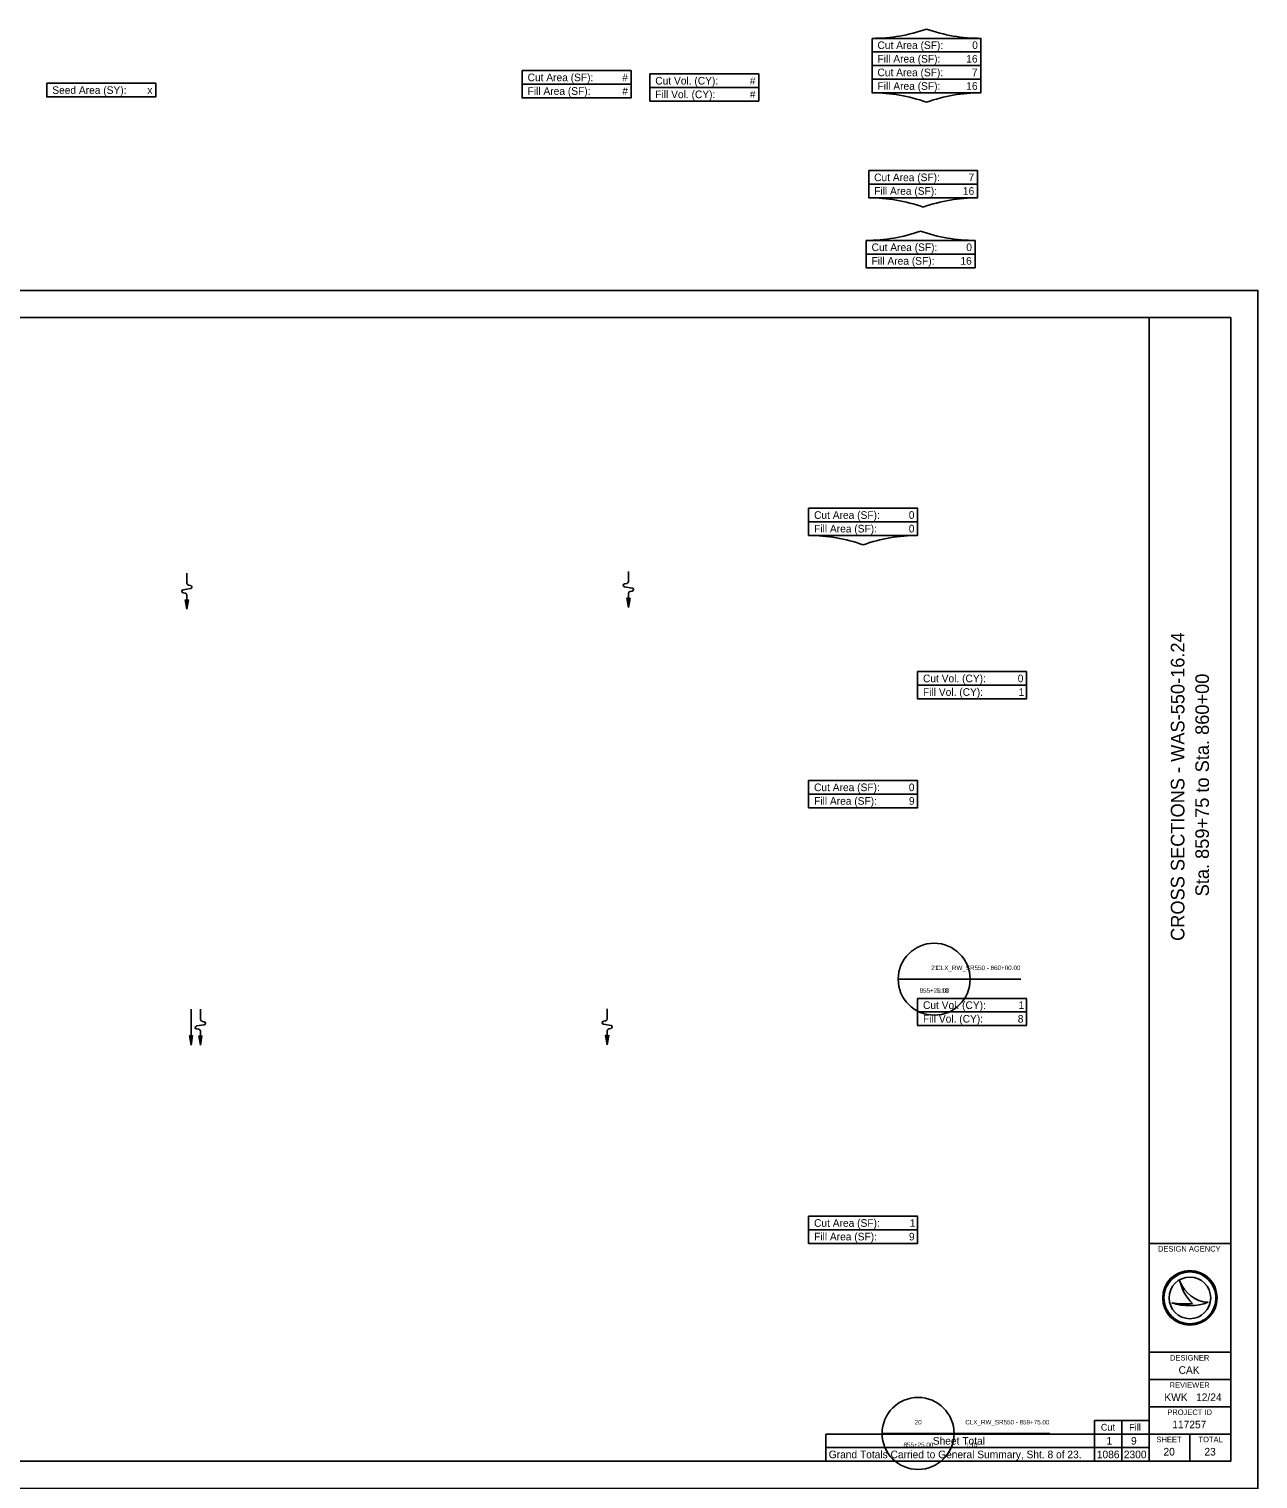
# Model space of a CAD drawing. Extents: x -475 to 76, y 0 to 417.
# Drawn here: x 11.44 to 34, y 198.17 to 224.8 of the extents above; entities that cross this region are included whole.
import ezdxf

# ---------------------------------------------------------------- set-up
doc = ezdxf.new("R2010")
doc.units = 0
for name, color, linetype in [('_CIVIL_CONSTRUCTION', 7, 'Continuous'), ('Default', 7, 'Continuous'), ('RW_P_Esmt_SH', 7, 'Continuous'), ('RW_P_Esmt_TMP', 7, 'Continuous'), ('SC_Scratch1', 7, 'Continuous'), ('SC_Scratch10', 7, 'Continuous'), ('SH_Masking', 7, 'Continuous')]:
    doc.layers.add(name, color=color, linetype=linetype)

msp = doc.modelspace()

# ---------------------------------------------------------------- linework, layer by layer
at = {"layer": '_CIVIL_CONSTRUCTION'}
for p, q in [((27.393, 207.352), (28.716, 207.352)), ((28.061, 207.352), (29.648, 207.352)), ((27.099, 199.01), (28.422, 199.01)), ((27.766, 199.01), (30.181, 199.01))]:
    msp.add_line(p, q, dxfattribs=at)
for centre in [(28.055, 207.352), (27.76, 199.01)]:
    msp.add_circle(centre, 0.661, dxfattribs=at)
at = {"layer": 'Default'}
for p, q in [((14.336, 214.808), (14.336, 214.623)), ((22.411, 214.618), (22.371, 214.611)), ((22.442, 214.84), (22.442, 214.655)), ((14.265, 214.447), (14.305, 214.439)), ((14.405, 214.523), (14.266, 214.502)), ((14.336, 214.402), (14.336, 214.146)), ((14.366, 214.586), (14.406, 214.579)), ((22.372, 214.555), (22.511, 214.534)), ((22.442, 214.178), (22.413, 214.352)), ((22.413, 214.352), (22.413, 214.352)), ((22.442, 214.435), (22.442, 214.178)), ((22.471, 214.351), (22.442, 214.178)), ((22.471, 214.351), (22.471, 214.351)), ((22.512, 214.479), (22.472, 214.471)), ((14.307, 214.319), (14.307, 214.319)), ((14.307, 214.319), (14.336, 214.146)), ((14.336, 214.146), (14.365, 214.32)), ((14.365, 214.32), (14.365, 214.32)), ((14.412, 206.804), (14.412, 206.142)), ((14.584, 206.8), (14.584, 206.615)), ((22.052, 206.809), (22.052, 206.624)), ((14.513, 206.439), (14.553, 206.432)), ((14.653, 206.515), (14.514, 206.495)), ((14.584, 206.395), (14.584, 206.138)), ((14.614, 206.578), (14.654, 206.571)), ((22.022, 206.587), (21.982, 206.58)), ((21.983, 206.524), (22.122, 206.504)), ((22.052, 206.404), (22.052, 206.147)), ((22.123, 206.448), (22.083, 206.441)), ((14.383, 206.315), (14.383, 206.315)), ((14.383, 206.315), (14.412, 206.142)), ((14.412, 206.142), (14.441, 206.316)), ((14.441, 206.316), (14.441, 206.316)), ((14.555, 206.312), (14.555, 206.312)), ((14.555, 206.312), (14.584, 206.138)), ((14.584, 206.138), (14.613, 206.312)), ((14.613, 206.312), (14.613, 206.312)), ((22.052, 206.147), (22.023, 206.321)), ((22.023, 206.321), (22.023, 206.321)), ((22.081, 206.321), (22.052, 206.147)), ((22.081, 206.321), (22.081, 206.321)), ((31, 198.5), (31, 199.25)), ((31.5, 198.5), (31.5, 199.25)), ((26.064, 198.5), (26.064, 199)), ((31, 198.5), (31, 199))]:
    msp.add_line(p, q, dxfattribs=at)
for centre, radius, start, end in [((14.373, 214.623), 0.0375, 180, 259.3803), ((22.376, 214.583), 0.0281, 100.6197, 261.4692), ((22.404, 214.655), 0.0375, 280.6197, 360), ((14.27, 214.474), 0.0281, 98.5308, 259.3803), ((14.298, 214.402), 0.0375, 0, 79.3803), ((14.401, 214.551), 0.0281, 278.5308, 79.3803), ((22.442, 214.396), 0.0527, 236.178, 302.8588), ((22.479, 214.435), 0.0375, 100.6197, 180), ((22.507, 214.507), 0.0281, 280.6197, 81.4692), ((14.335, 214.364), 0.0527, 237.1412, 303.822), ((22.015, 206.624), 0.0375, 280.6197, 360), ((14.518, 206.467), 0.0281, 98.5308, 259.3803), ((14.546, 206.395), 0.0375, 0, 79.3803), ((14.621, 206.615), 0.0375, 180, 259.3803), ((14.649, 206.543), 0.0281, 278.5308, 79.3803), ((21.987, 206.552), 0.0281, 100.6197, 261.4692), ((22.09, 206.404), 0.0375, 100.6197, 180), ((22.118, 206.476), 0.0281, 280.6197, 81.4692), ((14.411, 206.36), 0.0527, 237.1412, 303.822), ((14.583, 206.356), 0.0527, 237.1412, 303.822), ((22.053, 206.365), 0.0527, 236.178, 302.8588)]:
    msp.add_arc(centre, radius, start, end, dxfattribs=at)
at = {"layer": 'RW_P_Esmt_SH'}
msp.add_lwpolyline([(0, 198), (34, 198), (34, 220), (0, 220)], close=True, dxfattribs=at)
at = {"layer": 'RW_P_Esmt_TMP'}
for p, q in [((32, 198.5), (32, 219.5)), ((32, 202.5), (33.5, 202.5)), ((32, 200.5), (33.5, 200.5)), ((32, 200), (33.5, 200)), ((32, 199.5), (33.5, 199.5)), ((32, 199), (33.5, 199))]:
    msp.add_line(p, q, dxfattribs=at)
msp.add_lwpolyline([(1.5, 219.5), (33.5, 219.5), (33.5, 198.5), (1.5, 198.5)], close=True, dxfattribs=at)
at = {"layer": 'SC_Scratch1'}
for p, q in [((26.914, 224.628), (28.914, 224.628)), ((26.914, 224.628), (26.914, 224.128)), ((28.914, 224.628), (26.914, 224.628)), ((28.914, 224.628), (28.914, 224.128)), ((26.914, 224.378), (28.914, 224.378)), ((20.491, 224.036), (22.491, 224.036)), ((20.491, 224.036), (20.491, 223.536)), ((22.491, 224.036), (22.491, 223.536)), ((22.835, 223.975), (24.835, 223.975)), ((22.835, 223.975), (22.835, 223.475)), ((24.835, 223.975), (24.835, 223.475)), ((26.914, 224.128), (28.914, 224.128)), ((26.914, 224.128), (28.914, 224.128)), ((26.914, 224.128), (26.914, 223.628)), ((28.914, 224.128), (28.914, 223.628)), ((11.764, 223.803), (13.764, 223.803)), ((11.764, 223.803), (11.764, 223.553)), ((13.764, 223.803), (13.764, 223.553)), ((20.491, 223.786), (22.491, 223.786)), ((22.835, 223.725), (24.835, 223.725)), ((26.914, 223.878), (28.914, 223.878)), ((11.764, 223.553), (13.764, 223.553)), ((20.491, 223.536), (22.491, 223.536)), ((22.835, 223.475), (24.835, 223.475)), ((26.914, 223.628), (28.914, 223.628)), ((28.914, 223.628), (26.914, 223.628)), ((26.853, 222.201), (28.853, 222.201)), ((26.853, 222.201), (26.853, 221.701)), ((28.853, 222.201), (28.853, 221.701)), ((26.853, 221.951), (28.853, 221.951)), ((26.853, 221.701), (28.853, 221.701)), ((28.853, 221.701), (26.853, 221.701)), ((26.806, 220.917), (28.806, 220.917)), ((26.806, 220.917), (26.806, 220.417)), ((28.806, 220.917), (26.806, 220.917)), ((28.806, 220.917), (28.806, 220.417)), ((26.806, 220.667), (28.806, 220.667)), ((26.806, 220.417), (28.806, 220.417)), ((25.75, 216), (27.75, 216)), ((25.75, 216), (25.75, 215.5)), ((27.75, 216), (27.75, 215.5)), ((25.75, 215.75), (27.75, 215.75)), ((25.75, 215.5), (27.75, 215.5)), ((27.75, 215.5), (25.75, 215.5)), ((27.75, 213), (29.75, 213)), ((27.75, 213), (27.75, 212.5)), ((27.75, 212.75), (29.75, 212.75)), ((29.75, 213), (29.75, 212.5)), ((27.75, 212.5), (29.75, 212.5)), ((25.75, 211), (27.75, 211)), ((25.75, 211), (25.75, 210.5)), ((27.75, 211), (27.75, 210.5)), ((25.75, 210.75), (27.75, 210.75)), ((25.75, 210.5), (27.75, 210.5)), ((27.75, 207), (29.75, 207)), ((27.75, 207), (27.75, 206.5)), ((29.75, 207), (29.75, 206.5)), ((27.75, 206.75), (29.75, 206.75)), ((27.75, 206.5), (29.75, 206.5)), ((25.75, 203), (27.75, 203)), ((25.75, 203), (25.75, 202.5)), ((27.75, 203), (27.75, 202.5)), ((25.75, 202.75), (27.75, 202.75)), ((25.75, 202.5), (27.75, 202.5)), ((32.567, 201.81), (32.567, 201.81)), ((32.417, 201.41), (32.417, 201.41)), ((32.75, 201.5), (32.75, 201.5)), ((33.087, 201.419), (33.087, 201.419)), ((31, 199.25), (32, 199.25)), ((26.064, 199), (32, 199)), ((32.75, 198.5), (32.75, 199)), ((26.064, 198.75), (32, 198.75)), ((32.375, 198.675), (32.375, 198.675))]:
    msp.add_line(p, q, dxfattribs=at)
for radius in [0.5, 0.477, 0.477, 0.382]:
    msp.add_circle((32.75, 201.5), radius, dxfattribs=at)
for centre, radius, start, end in [((26.914, 227.628), 3, 270, 289.4712), ((28.914, 227.628), 3, 250.5288, 270), ((26.914, 220.628), 3, 70.5288, 90), ((28.914, 220.628), 3, 90, 109.4712), ((26.853, 218.701), 3, 70.5288, 90), ((28.853, 218.701), 3, 90, 109.4712), ((26.806, 223.917), 3, 270, 289.4712), ((28.806, 223.917), 3, 250.5288, 270), ((25.75, 212.5), 3, 70.5288, 90), ((27.75, 212.5), 3, 90, 109.4712), ((33.116, 201.998), 0.58, 198.9257, 198.9319), ((33.347, 201.97), 0.796, 191.6379, 191.6421), ((33.116, 201.998), 0.58, 198.9319, 267.1657), ((33.347, 201.97), 0.796, 191.6421, 226.0947), ((32.739, 202.37), 1.013, 251.4576, 290.0832), ((32.648, 202.654), 1.266, 259.4964, 259.4995), ((32.739, 202.37), 1.013, 251.4527, 251.4576), ((32.648, 202.654), 1.266, 259.4995, 276.6672)]:
    msp.add_arc(centre, radius, start, end, dxfattribs=at)
at = {"layer": 'SH_Masking'}
for points in [[(26.914, 224.628), (28.914, 224.628), (28.914, 224.128), (26.914, 224.128)], [(20.491, 224.036), (22.491, 224.036), (22.491, 223.536), (20.491, 223.536)], [(22.835, 223.975), (24.835, 223.975), (24.835, 223.475), (22.835, 223.475)], [(26.914, 224.128), (28.914, 224.128), (28.914, 223.628), (26.914, 223.628)], [(11.764, 223.803), (13.764, 223.803), (13.764, 223.553), (11.764, 223.553)], [(26.853, 222.201), (28.853, 222.201), (28.853, 221.701), (26.853, 221.701)], [(26.806, 220.917), (28.806, 220.917), (28.806, 220.417), (26.806, 220.417)], [(25.75, 216), (27.75, 216), (27.75, 215.5), (25.75, 215.5)], [(27.75, 213), (29.75, 213), (29.75, 212.5), (27.75, 212.5)], [(25.75, 211), (27.75, 211), (27.75, 210.5), (25.75, 210.5)], [(27.75, 207), (29.75, 207), (29.75, 206.5), (27.75, 206.5)], [(25.75, 203), (27.75, 203), (27.75, 202.5), (25.75, 202.5)]]:
    msp.add_lwpolyline(points, close=True, dxfattribs=at)

# ---------------------------------------------------------------- texts
at = {"layer": '_CIVIL_CONSTRUCTION'}
for s, height, p in [('21', 0.0833, (28.001, 207.519)), ('CLX_RW_SR550 - 860+00.00', 0.08333, (28.093, 207.519)), ('855+25.00', 0.0833, (27.787, 207.102)), ('1:10', 0.0833, (28.093, 207.102)), ('20', 0.0833, (27.698, 199.176)), ('CLX_RW_SR550 - 859+75.00', 0.08333, (28.626, 199.176)), ('855+25.00', 0.0833, (27.492, 198.76)), ('1:10', 0.0833, (28.626, 198.76))]:
    msp.add_text(s, height=height, dxfattribs=at).set_placement(p)
at = {"layer": 'Default'}
for s, height, p in [('Cut', 0.125, (31.115, 199.062)), ('Fill', 0.125, (31.635, 199.062)), ('Sheet Total', 0.14, (28.03, 198.805)), ('1', 0.14, (31.218, 198.805)), ('9', 0.14, (31.669, 198.805)), ('Grand Totals Carried to General Summary, Sht. 8 of 23.', 0.14, (26.12, 198.555)), ('1086', 0.14, (31.041, 198.555)), ('2300', 0.14, (31.537, 198.555))]:
    msp.add_text(s, height=height, dxfattribs=at).set_placement(p)
at = {"layer": 'SC_Scratch1'}
for s, p in [('CROSS SECTIONS - WAS-550-16.24', (32.65, 208.055)), ('Sta. 859+75 to Sta. 860+00', (33.1, 208.873))]:
    msp.add_text(s, height=0.25, rotation=90, dxfattribs=at).set_placement(p)
for s, height, p in [('DESIGN AGENCY', 0.1, (32.163, 202.35)), ('DESIGNER', 0.1, (32.385, 200.35)), ('CAK', 0.14, (32.542, 200.105)), ('KWK   12/24', 0.14, (32.281, 199.605)), ('REVIEWER', 0.1, (32.377, 199.85)), ('PROJECT ID', 0.1, (32.335, 199.35)), ('117257', 0.14, (32.427, 199.105)), ('SHEET', 0.1, (32.135, 198.85)), ('TOTAL', 0.1, (32.908, 198.85)), ('20', 0.14, (32.265, 198.605)), ('23', 0.14, (33.016, 198.605))]:
    msp.add_text(s, height=height, dxfattribs=at).set_placement(p)
at = {"layer": 'SC_Scratch10'}
for s, p in [('Cut Area (SF):', (27.014, 224.433)), ('0', (28.753, 224.433)), ('Fill Area (SF):', (27.014, 224.183)), ('16', (28.644, 224.183)), ('Cut Area (SF):', (20.591, 223.841)), ('#', (22.328, 223.841)), ('Cut Vol. (CY):', (22.935, 223.78)), ('Cut Area (SF):', (27.014, 223.933)), ('7', (28.747, 223.933)), ('Seed Area (SY):', (11.864, 223.608)), ('x', (13.609, 223.608)), ('Fill Area (SF):', (20.591, 223.591)), ('#', (22.328, 223.591)), ('Fill Vol. (CY):', (22.935, 223.53)), ('#', (24.671, 223.78)), ('#', (24.671, 223.53)), ('Fill Area (SF):', (27.014, 223.683)), ('16', (28.644, 223.683)), ('Cut Area (SF):', (26.953, 222.006)), ('7', (28.686, 222.006)), ('Fill Area (SF):', (26.953, 221.756)), ('16', (28.583, 221.756)), ('Cut Area (SF):', (26.906, 220.722)), ('0', (28.645, 220.722)), ('Fill Area (SF):', (26.906, 220.472)), ('16', (28.536, 220.472)), ('Cut Area (SF):', (25.85, 215.805)), ('0', (27.589, 215.805)), ('Fill Area (SF):', (25.85, 215.555)), ('0', (27.589, 215.555)), ('Cut Vol. (CY):', (27.85, 212.805)), ('0', (29.589, 212.805)), ('Fill Vol. (CY):', (27.85, 212.555)), ('1', (29.606, 212.555)), ('Cut Area (SF):', (25.85, 210.805)), ('0', (27.589, 210.805)), ('Fill Area (SF):', (25.85, 210.555)), ('9', (27.592, 210.555)), ('Cut Vol. (CY):', (27.85, 206.805)), ('1', (29.606, 206.805)), ('Fill Vol. (CY):', (27.85, 206.555)), ('8', (29.59, 206.555)), ('Cut Area (SF):', (25.85, 202.805)), ('1', (27.606, 202.805)), ('Fill Area (SF):', (25.85, 202.555)), ('9', (27.592, 202.555))]:
    msp.add_text(s, height=0.14, dxfattribs=at).set_placement(p)

doc.saveas('drawing.dxf')
